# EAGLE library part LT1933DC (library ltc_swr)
LT1933 - 600mA, 500kHz Step-Down Switching Regulator in DFN6 Wide Input Range: 3.6V to 36V 5V at 600mA from 16V to 36V Input 3.3V at 600mA from 12V to 36V Input 5V at 500mA from 6.3V to 36V Input 3.3V at 500mA from 4.5V to 36V Input Fixed Frequency 500kHz Operation Uses Tiny Capacitors and Inductors Soft-Start Internally Compensated Low Shutdown Current: <2&micro;A Output Adjustable Down to 1.25V Low Profile (1mm) SOT-23 (ThinSOT&trade;) and (2mm x 3mm x 0.75mm) 6-Pin DFN Packages
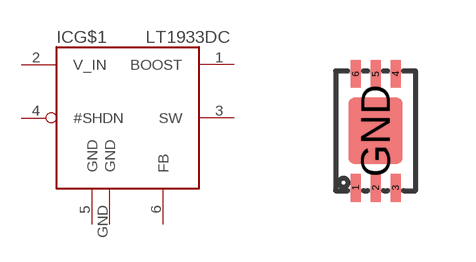
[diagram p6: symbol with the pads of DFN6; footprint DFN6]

Designator prefix IC; gates G$1=LT1616 G$2=LT3475_SUP

## LT1933DC  [DFN6]
1  G$1:BOOST  pas
2  G$1:V_IN  pas
3  G$1:SW  pas
4  G$1:#SHDN  pas
5  G$1:GND  pwr
6  G$1:FB  pas
GND  G$2:GND  pwr

## Footprint DFN6 (pad centres in mm)
smd 0.25 x 0.7: 1 -0.5,-1.425; 2 0,-1.425; 3 0.5,-1.425; 4 0.5,1.425; 5 0,1.425; 6 -0.5,1.425
smd 1.35 x 1.65: GND 0,0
